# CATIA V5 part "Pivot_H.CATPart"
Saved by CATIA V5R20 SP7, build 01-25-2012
Part number: Pivot_H
Bounding box of the stored display mesh (mm): x -152.5 to -147.5, y -2.5 to 2.5, z -6 to 6
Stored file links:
  D:\IFMA\COURS\2A\projet balance IAO\catia\Pivot_H.CATPart
  D:\IFMA\COURS\2A\projet balance IAO\catia\Ass_projet_balance.CATProduct
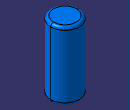
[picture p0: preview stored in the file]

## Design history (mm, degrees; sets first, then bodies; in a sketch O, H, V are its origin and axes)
Set1
  Plane1 "Plan_plateau_gauche": linked copy from another document
  Point1 "Point.H": linked copy from another document
  Plane2 "Plan.KDAF": linked copy from another document
  Point2 "Point.D": linked copy from another document
Body1 (main body)
  Sketch1 on Plane1, origin (0, 0, 0), H (1, 0, 0), V (0, 1, 0)
    circle A1 centre (-150, 0) radius 2.5
    point P1 (-150, 0)
    reference projected point E1 (-150, 0) from Point1
    radius A1 = 2.5
    coincidence: P1 E1
  Pad1: profile Sketch1, direction (0, 0, 1), length 6, mirrored extent
  Fillet1: radius 0.5, on edge [face of Pad1 from Sketch1.A1 | end face of Pad1]; edge [start face of Pad1 | face of Pad1 from Sketch1.A1]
